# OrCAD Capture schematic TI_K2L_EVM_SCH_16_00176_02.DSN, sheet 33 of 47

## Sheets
33 PAGE46 : K2L_POWER SECTION 5: size C; title: K2L VDDALV, v85 filter, bypass caps, 12v -> 3.3vaux
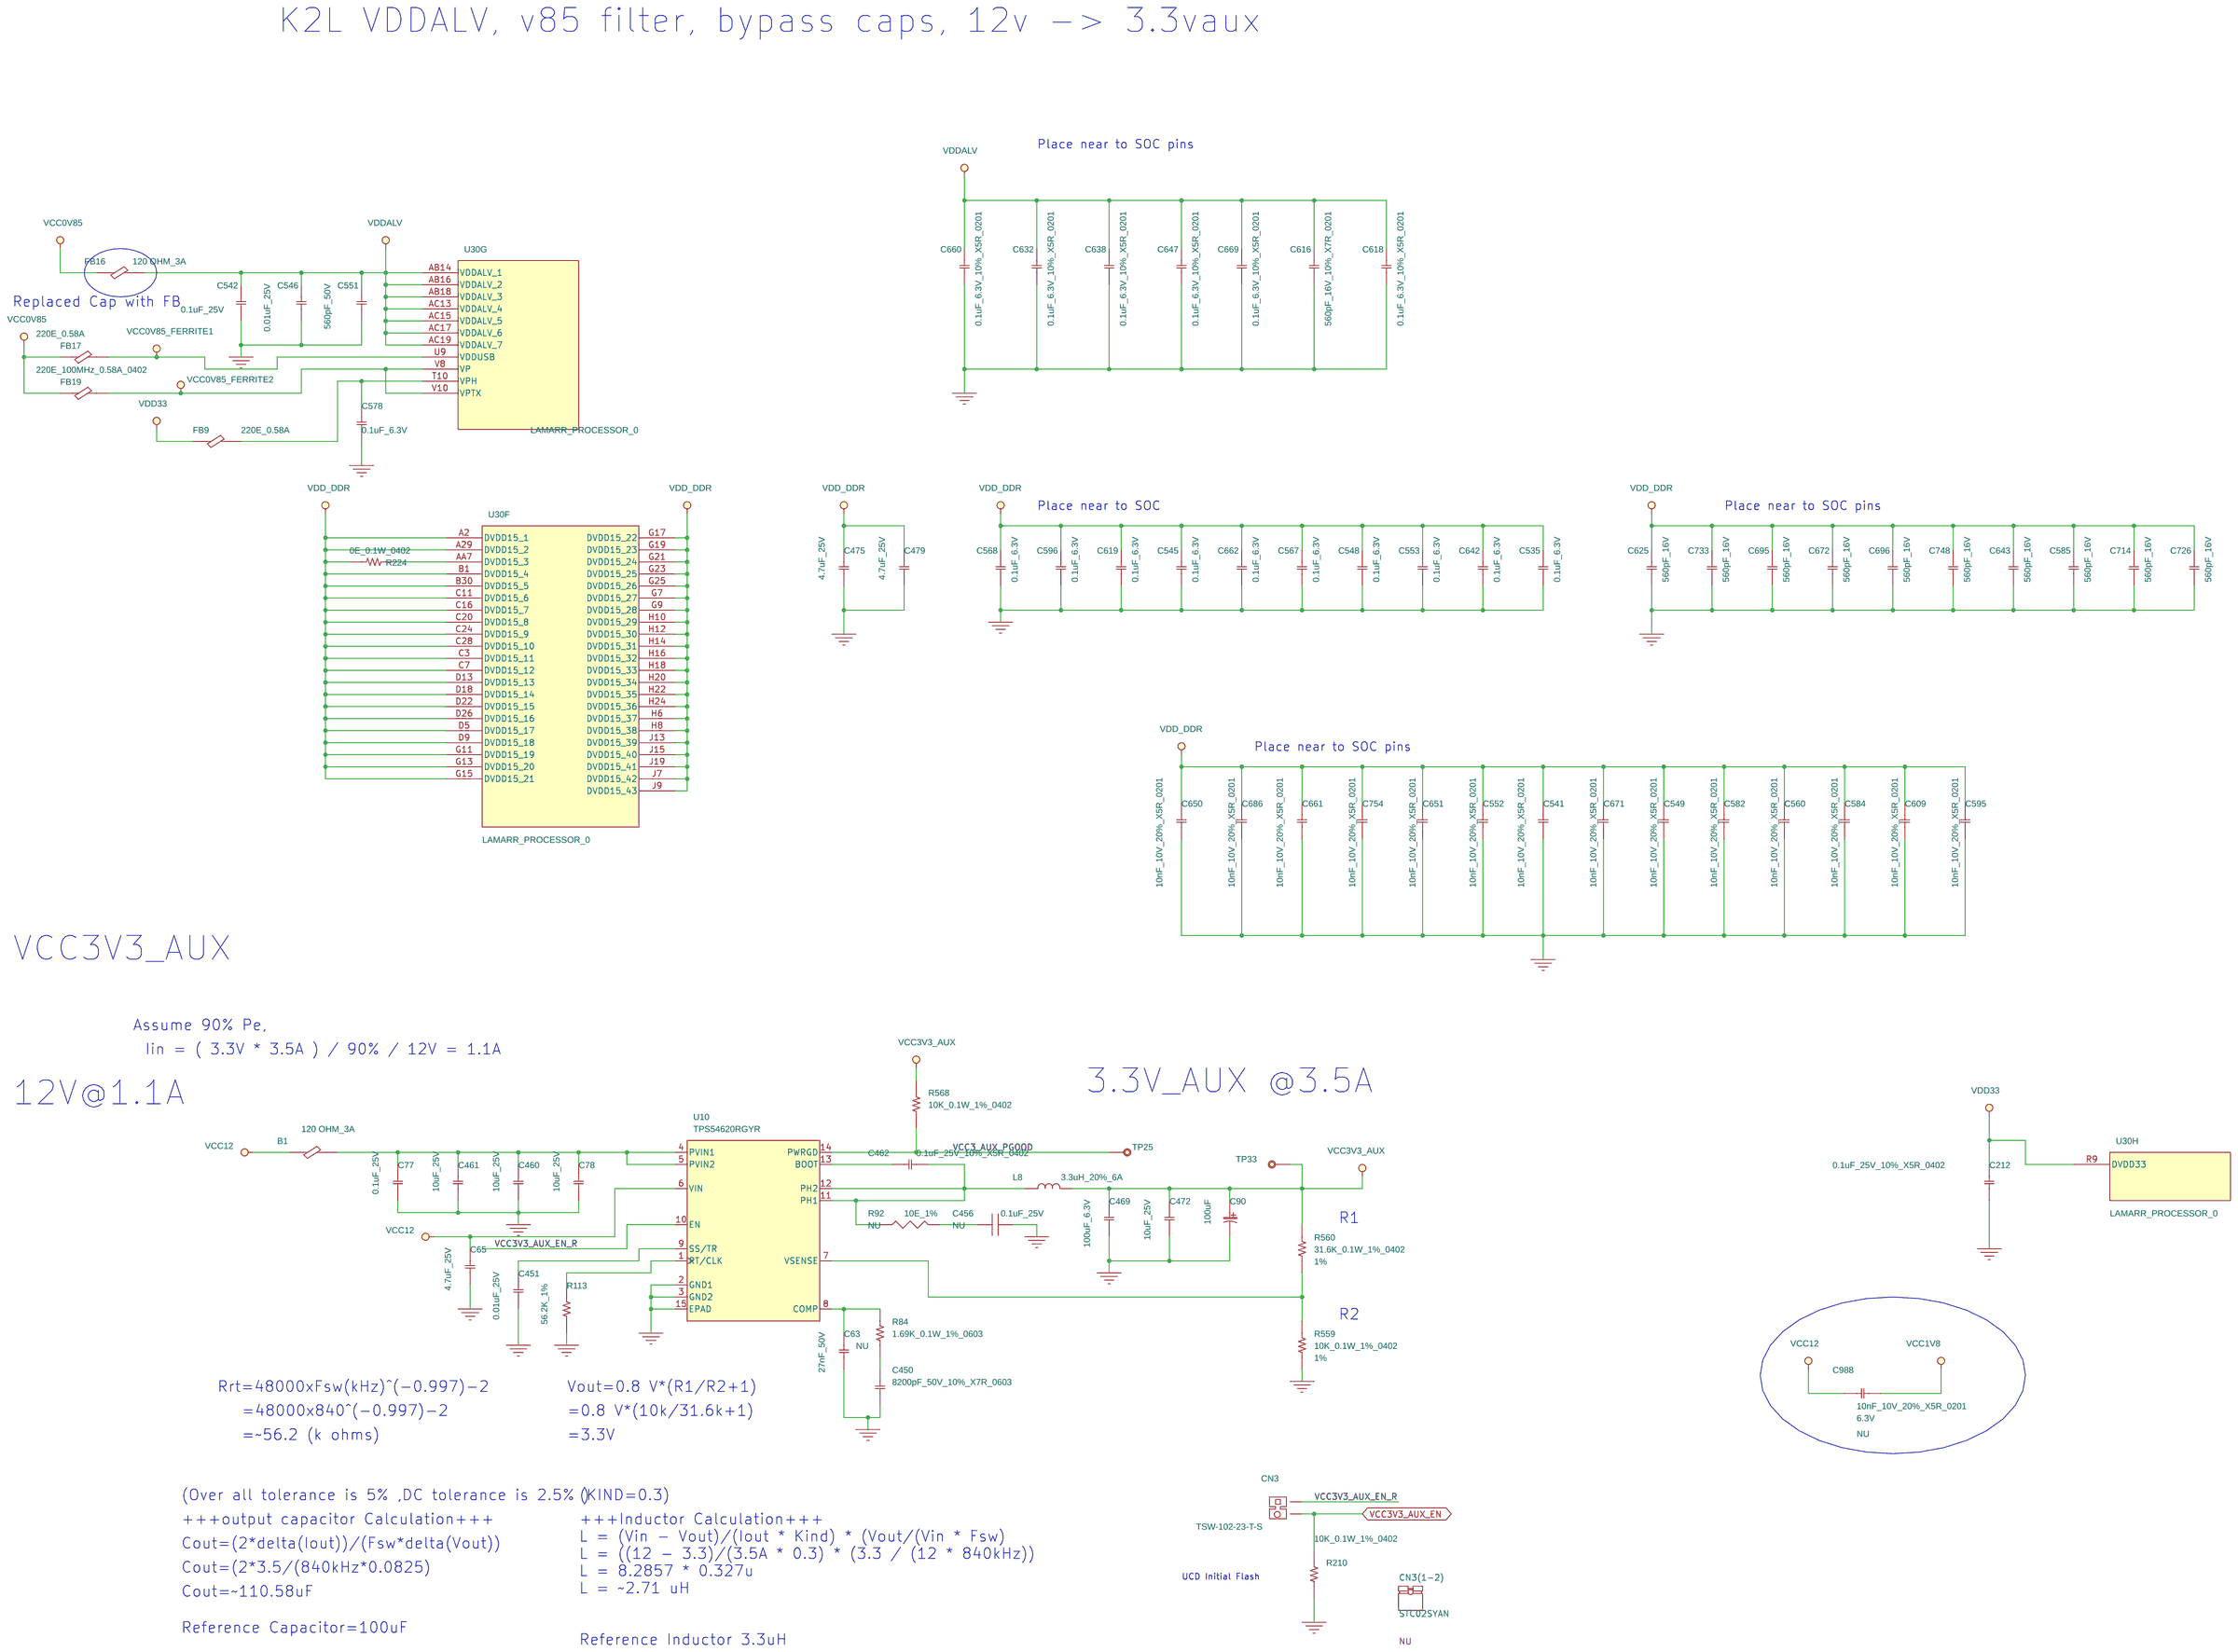
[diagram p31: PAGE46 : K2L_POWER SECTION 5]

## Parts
sheet PAGE24 : K2L_JTAG
U30  LAMARR_PROCESSOR_0  [SKTBGA_Z3566_SS900-RHFB-BGA080]  (sections A,B,C,D,E,F,G,H,I,J,K,L,M,N,O,P,Q,R,S,T,U)
sheet PAGE46 : K2L_POWER SECTION 5
B1  120 OHM_3A  [L0603]
C63  27nF_50V  [C0805]
C65  4.7uF_25V  [C0603]
C77  0.1uF_25V  [C0402]
C78  10uF_25V  [C0603]
C90  100uF  [CT7343]
C212  0.1uF_25V_10%_X5R_0402  [C0402]
C450  8200pF_50V_10%_X7R_0603  [C0603]
C451  0.01uF_25V  [C0402]
C456  0.1uF_25V  [C0402]
C460  10uF_25V  [C0603]
C461  10uF_25V  [C0603]
C462  0.1uF_25V_10%_X5R_0402  [C0402]
C469  100uF_6.3V  [C1206-1]
C472  10uF_25V  [C0603]
C475  4.7uF_25V  [C0603]
C479  4.7uF_25V  [C0603]
C535  0.1uF_6.3V  [CC0201_IPC7351_EINF]
C541  10nF_10V_20%_X5R_0201  [CC0201_IPC7351_EINF]
C542  0.1uF_25V  [C0402]
C545  0.1uF_6.3V  [CC0201_IPC7351_EINF]
C546  0.01uF_25V  [C0402]
C548  0.1uF_6.3V  [CC0201_IPC7351_EINF]
C549  10nF_10V_20%_X5R_0201  [CC0201_IPC7351_EINF]
C551  560pF_50V  [C0402]
C552  10nF_10V_20%_X5R_0201  [CC0201_IPC7351_EINF]
C553  0.1uF_6.3V  [CC0201_IPC7351_EINF]
C560  10nF_10V_20%_X5R_0201  [CC0201_IPC7351_EINF]
C567  0.1uF_6.3V  [CC0201_IPC7351_EINF]
C568  0.1uF_6.3V  [CC0201_IPC7351_EINF]
C578  0.1uF_6.3V  [CC0201_IPC7351_EINF]
C582  10nF_10V_20%_X5R_0201  [CC0201_IPC7351_EINF]
C584  10nF_10V_20%_X5R_0201  [CC0201_IPC7351_EINF]
C585  560pF_16V  [CC0201_IPC7351_EINF]
C595  10nF_10V_20%_X5R_0201  [CC0201_IPC7351_EINF]
C596  0.1uF_6.3V  [CC0201_IPC7351_EINF]
C609  10nF_10V_20%_X5R_0201  [CC0201_IPC7351_EINF]
C616  560pF_16V_10%_X7R_0201  [CC0201_IPC7351_EINF]
C618  0.1uF_6.3V_10%_X5R_0201  [CC0201_IPC7351_EINF]
C619  0.1uF_6.3V  [CC0201_IPC7351_EINF]
C625  560pF_16V  [CC0201_IPC7351_EINF]
C632  0.1uF_6.3V_10%_X5R_0201  [CC0201_IPC7351_EINF]
C638  0.1uF_6.3V_10%_X5R_0201  [CC0201_IPC7351_EINF]
C642  0.1uF_6.3V  [CC0201_IPC7351_EINF]
C643  560pF_16V  [CC0201_IPC7351_EINF]
C647  0.1uF_6.3V_10%_X5R_0201  [CC0201_IPC7351_EINF]
C650  10nF_10V_20%_X5R_0201  [CC0201_IPC7351_EINF]
C651  10nF_10V_20%_X5R_0201  [CC0201_IPC7351_EINF]
C660  0.1uF_6.3V_10%_X5R_0201  [CC0201_IPC7351_EINF]
C661  10nF_10V_20%_X5R_0201  [CC0201_IPC7351_EINF]
C662  0.1uF_6.3V  [CC0201_IPC7351_EINF]
C669  0.1uF_6.3V_10%_X5R_0201  [CC0201_IPC7351_EINF]
C671  10nF_10V_20%_X5R_0201  [CC0201_IPC7351_EINF]
C672  560pF_16V  [CC0201_IPC7351_EINF]
C686  10nF_10V_20%_X5R_0201  [CC0201_IPC7351_EINF]
C695  560pF_16V  [CC0201_IPC7351_EINF]
C696  560pF_16V  [CC0201_IPC7351_EINF]
C714  560pF_16V  [CC0201_IPC7351_EINF]
C726  560pF_16V  [CC0201_IPC7351_EINF]
C733  560pF_16V  [CC0201_IPC7351_EINF]
C748  560pF_16V  [CC0201_IPC7351_EINF]
C754  10nF_10V_20%_X5R_0201  [CC0201_IPC7351_EINF]
C988  10nF_10V_20%_X5R_0201  [CC0201_IPC7351_EINF]
CN3  TSW-102-23-T-S  [SAMTSW-102-22-T-S]
CN3(1-2)  STC02SYAN  [NA]
FB9  220E_0.58A  [L0402]
FB16  120 OHM_3A  [L0603]
FB17  220E_0.58A  [L0402]
FB19  220E_100MHz_0.58A_0402  [L0402]
L8  3.3uH_20%_6A  [IND_ASPI-7318-2R2M-T]
R84  1.69K_0.1W_1%_0603  [R0603]
R92  10E_1%  [R0402]
R113  56.2K_1%  [R0402]
R210  10K_0.1W_1%_0402  [R0402]
R224  0E_0.1W_0402  [R0402]
R559  10K_0.1W_1%_0402  [R0402]
R560  31.6K_0.1W_1%_0402  [R0402]
R568  10K_0.1W_1%_0402  [R0402]
TP25  TP  [TP-S40]
TP33  TP  [TP-S40]
U10  TPS54620RGYR  [QFN_14P_20_138x138_TP79]

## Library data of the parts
U30 = LAMARR_PROCESSOR_7: LAMARR-SoC 900BGA 4DSP + 2ARM; Color: Default; Distributor_name: TBD; Distributor_part_number: TBD; EIC Part#: TBD; Location X-Coordinate: 0; Location Y-Coordinate: 0; Manufacture: TI; Manufacture Part Number: TCI6630K2L; Manufacture(English): TI; Manufacture_Part_Number: TCI6630K2L; Manufacturer: TI; Manufacturer_Part_No: TCI6630K2L; Mfg: TI; Mfg Part#: TBD; Mfr_name: TI; Mfr_part_number: LAMARR-SoC; Price @ 1: TBD; Price @ 10K: TBD; Price @ 1K: TBD; Primitive: DEFAULT; SPLIT_INST: TRUE; SWAP_INFO: (S1+S2+S3+S4+S5+S6+S7+S8+S9+S10+S11+S12+S13+S14+S15+S16+S17+S18+S19+S20+S21); Vendor: TBD; Vendor_Part_No: TBD; eI Part#: TBD
B1 FB16 = 1212_BEAD_0: FILTER CHIP 120 OHM 3A 0603; Distributor_name: DIGIKEY; Distributor_part_number: 490-3996-1-ND; EIC Part#: 04_00405_01; Manufacture: Murata; Manufacture Part Number: BLM18SG121TN1D; Manufacture(English): Murata; Manufacture_Part_Number: BLM18SG121TN1D; Manufacturer: Murata; Manufacturer_Part_No: BLM18SG121TN1D; Mfg: Murata Electronics North America; Mfg Part#: 04_00405_01; Mfr_name: Murata; Mfr_part_number: BLM18SG121TN1D; Part_Number: 1212002506; Price @ 1: 0.14000; Price @ 10K: 0.03173; Price @ 1K: 0.03878; RoHS: Yes; Vendor: DIGIKEY; Vendor Part#: 490-3996-1-ND; Vendor_Part_No: 490-3996-1-ND; eI Part#: 04_00405_01
C63 = 11_C_0: CAP CER 0.027UF 50V 10% X7R 0805; Distributor_name: DIGIKEY; Distributor_part_number: 311-1139-1-ND; EIC Part#: 03_00588_01; Manufacture: Yageo; Manufacture Part Number: CC0805KRX7R9BB273; Manufacture(English): Yageo; Manufacture_Part_Number: CC0805KRX7R9BB273; Manufacturer: Yageo; Manufacturer_Part_No: CC0805KRX7R9BB273; Mfg: Yageo; Mfg Part#: 03_00588_01; Mfr_name: Yageo; Mfr_part_number: CC0805KRX7R9BB273; Mounting Status: NU; Mounting_Status: NU; Oper. Temp. Range: -55C ~ 125C; Package: 0805; Price @ 1: 0.10000; Price @ 10K: 0.01320; Price @ 1K: 0.01722; ProcessType: SMT; RoHS: Yes; Tolerance: 10%; Vendor: DIGIKEY; Vendor Part#: 311-1139-1-ND; Vendor_Part_No: 311-1139-1-ND; Voltage: 50V; eI Part#: 03_00588_01
C65 = 11_C_0: CAP CER 4.7UF 25V 20% X5R 0603; Distributor_name: DIGIKEY; Distributor_part_number: 1276-1903-2-ND; EIC Part#: 03_00592_01; Manufacture: Samsung; Manufacture Part Number: CL10A475MA8NQNC; Manufacture(English): Samsung; Manufacture_Part_Number: CL10A475MA8NQNC; Manufacturer: Samsung; Manufacturer_Part_No: CL10A475MA8NQNC; Mfg: Samsung; Mfg Part#: CL10A475MA8NQNC; Mfr_name: Samsung; Mfr_part_number: CL10A475MA8NQNC; Oper. Temp. Range: -55C to 85C; Package: 0603; Price @ 1: 0.24000; Price @ 10K: 0.05000; Price @ 1K: 0.05875; ProcessType: SMT; RoHS: Yes; Tolerance: 10%; Vendor: DIGIKEY; Vendor Part#: 1276-1903-2-ND; Vendor_Part_No: 1276-1903-2-ND; Voltage: 25V; eI Part#: 03_00592_01
C77 C462 = 11_C_0: CAP CER 0.1UF 25V 10% X5R 0402; Avalue_Part_Number: E1123510400H; Distributor_name: DIGIKEY; Distributor_part_number: 445-4964-1-ND; EIC Part#: 03_00470_02; Manufacture: TDK Corporation; Manufacture Part Number: C1005X5R1E104K050BC; Manufacture(English): TDK Corporation; Manufacture_Part_Number: GRM155R71C104KA88D; Manufacturer: TDK Corporation; Manufacturer_Part_No: C1005X5R1E104K050BC; Mfg: Murata Electronics North America; Mfg Part#: 03_00470_02; Mfr_name: TDK Corporation; Mfr_part_number: C1005X5R1E104K050BC; Package: 0402; Price @ 1: 0.10000; Price @ 1K: 0.00420; ProcessType: SMT; Tolerance: 10%; Vendor: DIGIKEY; Vendor Part#: 445-4964-1-ND; Vendor_Part_No: 445-4964-1-ND; eI Part#: 03_00470_02
C78 C460 C461 = 11_C_0: CAP CER 10UF 25V 20% X5R 0603; Advansus_Part_Number: 11G235210611320; Avalue_Part_Number: E1123510620H; Characteristic: 16V; Distributor_name: DIGIKEY; Distributor_part_number: 445-9015-1-ND; EIC Part#: 03_00609_01; Manufacture: TDK Corporation; Manufacture Part Number: C1608X5R1E106M080AC; Manufacture(English): TDK Corporation; Manufacture_Part_Number: C1608X5R1E106M080AC; Manufacturer: TDK Corporation; Manufacturer_Part_No: C1608X5R1E106M080AC; Mfg: TDK Corporation; Mfg Part#: C1608X5R1E106M080AC; Mfr_name: TDK Corporation; Mfr_part_number: C1608X5R1E106M080AC; Package: 0603; Price @ 1: 0.24000; Price @ 10K: 0.05000; Price @ 1K: 0.05875; ProcessType: SMT; Tolerance: 10%; Vendor: DIGIKEY; Vendor Part#: TDK Corporation; Vendor_Part_No: 445-9015-1-ND; eI Part#: 03_00609_01
C90 = 11_C_POLAR_0: CAP TANT 100UF 20V 10% 2917; Characteristic: 16V; Distributor_name: DIGIKEY; Distributor_part_number: 718-1774-1-ND; EIC Part#: 03_00602_01; Manufacture: Vishay; Manufacture Part Number: TR3D107K020C0080; Manufacture(English): Vishay Dale; Manufacture_Part_Number: TR3D107K020C0080; Manufacturer: Vishay Dale; Manufacturer_Part_No: TR3D107K020C0080; Mfg: Vishay Dale; Mfg Part#: TR3D107K020C0080; Mfr_name: Vishay Dale; Mfr_part_number: TR3D107K020C0080; Package: 7343; Price @ 1: 1.05000; Price @ 10K: 0.29063; Price @ 1K: 0.29063; ProcessType: SMT; RoHS: Yes; Tolerance: 20%; Vendor: DIGIKEY; Vendor Part#: 718-1774-1-ND; Vendor_Part_No: 718-1774-1-ND; eI Part#: 03_00602_01
C212 C542 = 11_C_12: CAP CER 0.1UF 25V 10% X5R 0402; Alt Mfg: Taiyo Yuden; Distributor_name: DIGIKEY; Distributor_part_number: 445-4964-1-ND; EIC Part#: 03_00470_02; Manufacture: TDK Corporation; Manufacture Part Number: C1005X5R1E104K050BC; Manufacture(English): TDK Corporation; Manufacture_Part_Number: GRM155R61E104KA87D; Manufacturer: TDK Corporation; Manufacturer_Part_No: C1005X5R1E104K050BC; Mfg: Murata Electronics North America; Mfg Part#: 03_00470_02; Mfr_name: TDK Corporation; Mfr_part_number: C1005X5R1E104K050BC; Oper. Temp. Range: -55°C ~ 85°C; Package: 0402; Price @ 1: 0.10000; Price @ 1K: 0.00960; ProcessType: SMT; RoHS: Yes; Tolerance: 10%; Vendor: DIGIKEY; Vendor Part#: 445-4964-1-ND; Vendor_Part_No: 445-4964-1-ND; eI Part#: 03_00470_02
C450 = 11_C_0: CAP CER 8200PF 50V 10% X7R 0603; Characteristic: 50V; Distributor_name: DIGIKEY; Distributor_part_number: 490-1510-1-ND; EIC Part#: 03_00232_02; Manufacture: Murata; Manufacture Part Number: GRM188R71H822KA01D; Manufacture(English): Murata; Manufacture_Part_Number: GRM188R71H822KA01D; Manufacturer: Murata; Manufacturer_Part_No: GRM188R71H822KA01D; Mfg: Murata Electronics North America; Mfg Part#: 03_00232_02; Mfr_name: Murata; Mfr_part_number: GRM188R71H822KA01D; Package: 0603; Part_Number: 1124582280; Price @ 1: 0.11000; Price @ 10K: 0.01541; Price @ 1K: 0.02010; ProcessType: SMT; Tolerance: 10%; Vendor: DIGIKEY; Vendor_Part_No: 490-1510-1-ND; eI Part#: 03_00232_02
C451 = 11_C_0: CAP CER 10000PF 25V 10% X7R 0402; Advansus_Part_Number: 11G232110312030; Characteristic: 16V; Distributor_name: DIGIKEY; Distributor_part_number: 445-1260-1-ND; EIC Part#: 03_00029_04; Manufacture: TDK Corporation; Manufacture Part Number: C1005X7R1E103K; Manufacture(English): TDK Corporation; Manufacture_Part_Number: C1005X7R1E103K; Manufacturer: TDK Corporation; Manufacturer_Part_No: C1005X7R1E103K; Mfg: TDK Corporation; Mfg Part#: 03_00029_04; Mfr_name: TDK Corporation; Mfr_part_number: C1005X7R1E103K; Package: 0402; Part_Number: 1121610790; Price @ 1: 0.10000; Price @ 10K: 0.00420; Price @ 1K: 0.00600; ProcessType: SMT; Tolerance: 10%; Vendor: DIGIKEY; Vendor_Part_No: 445-1260-1-ND; eI Part#: 03_00029_04
C456 = CAP_NP: CAP CER 0.1UF 25V 10% X5R 0402; Alt Mfg: Taiyo Yuden; Distributor_name: DIGIKEY; Distributor_part_number: 445-4964-1-ND; EIC Part#: 03_00470_02; Manufacture: TDK Corporation; Manufacture Part Number: C1005X5R1E104K050BC; Manufacture(English): TDK Corporation; Manufacture_Part_Number: GRM155R61E104KA87D; Manufacturer: TDK Corporation; Manufacturer_Part_No: C1005X5R1E104K050BC; Mfg: Murata Electronics North America; Mfg Part#: 03_00470_02; Mfr_name: TDK Corporation; Mfr_part_number: C1005X5R1E104K050BC; Mounting Status: NU; Mounting_Status: NU; Oper. Temp. Range: -55°C ~ 85°C; Package: 0402; Price @ 1: 0.10000; Price @ 1K: 0.00960; RoHS: Yes; Vendor: DIGIKEY; Vendor Part#: 445-4964-1-ND; Vendor_Part_No: 445-4964-1-ND; eI Part#: 03_00470_02
C469 = 11_C_0: CAP CER 100UF 6.3V 20% X5R 1206; Characteristic: 6.3V; Distributor_name: DIGIKEY; Distributor_part_number: 587-1453-1-ND; EIC Part#: 03_00380_04; Manufacture: Taiyo Yuden; Manufacture Part Number: JMK316BJ107ML-T; Manufacture(English): Taiyo Yuden; Manufacture_Part_Number: JMK316BJ107ML-T; Manufacturer: Taiyo Yuden; Manufacturer_Part_No: JMK316BJ107ML-T; Mfg: Taiyo Yuden; Mfg Part#: 03_00380_04; Mfr_name: Taiyo Yuden; Mfr_part_number: JMK316BJ107ML-T; Package: 1206; Part_Number: 1100005026; Price @ 1: 1.80000; Price @ 10K: 0.30450; Price @ 1K: 0.43050; ProcessType: SMT; Tolerance: 20%; Vendor: DIGIKEY; Vendor_Part_No: 587-1453-1-ND; Voltage: 6.3V; eI Part#: 03_00380_04
C472 = 11_C_0: CAP CER 10UF 25V 20% X5R 0603; Characteristic: 6.3V; Distributor_name: DIGIKEY; Distributor_part_number: 445-9015-1-ND; EIC Part#: 03_00609_01; Manufacture: TDK Corporation; Manufacture Part Number: C1608X5R1E106M080AC; Manufacture(English): TDK Corporation; Manufacture_Part_Number: C1608X5R1E106M080AC; Manufacturer: TDK Corporation; Manufacturer_Part_No: C1608X5R1E106M080AC; Mfg: TDK Corporation; Mfg Part#: C1608X5R1E106M080AC; Mfr_name: TDK Corporation; Mfr_part_number: C1608X5R1E106M080AC; Package: 0603; Price @ 1: 0.35000; Price @ 10K: 0.07300; Price @ 1K: 0.08578; ProcessType: SMT; Tolerance: 10%; Vendor: DIGIKEY; Vendor Part#: TDK Corporation; Vendor_Part_No: 445-9015-1-ND; eI Part#: 03_00609_01
C475 C479 = 11_C_12: CAP CER 4.7UF 25V 20% X5R 0603; Characteristic: <Characteristic>; Distributor_name: DIGIKEY; Distributor_part_number: 1276-1903-2-ND; EIC Part#: 03_00592_01; Manufacture: Samsung; Manufacture Part Number: CL10A475MA8NQNC; Manufacture(English): Samsung; Manufacture_Part_Number: CL10A475MA8NQNC; Manufacturer: Samsung; Manufacturer_Part_No: CL10A475MA8NQNC; Mfg: Samsung; Mfg Part#: CL10A475MA8NQNC; Mfr_name: Samsung; Mfr_part_number: CL10A475MA8NQNC; Oper. Temp. Range: -55C to 85C; Package: 0603; Price @ 1: 0.16000; Price @ 10K: 0.02322; Price @ 1K: 0.02970; ProcessType: SMT; RoHS: Yes; Tolerance: 10%; Vendor: DIGIKEY; Vendor Part#: 1276-1903-2-ND; Vendor_Part_No: 1276-1903-2-ND; Voltage: 6.3V; eI Part#: 03_00592_01
C535 C545 C548 C553 C567 C568 C596 C618 C619 C632 C638 C642 C647 C660 C662 C669 = 11_C_12: CAP CER 0.1UF 6.3V 10% X5R 0201; Alt Mfg: Taiyo Yuden; Alt Mfg Part#: TMK105BJ104KV-F; Characteristic: <Characteristic>; Distributor_name: DIGIKEY; Distributor_part_number: 445-1796-1-ND; EIC Part#: 03_00583_01; Manufacture: TDK Corporation; Manufacture Part Number: C0603X5R0J104K030BC; Manufacture(English): TDK Corporation; Manufacture_Part_Number: C0603X5R0J104K030BC; Manufacturer: TDK Corporation; Manufacturer_Part_No: C0603X5R0J104K030BC; Mfg: TDK Corporation; Mfg Part#: 03_00583_01; Mfr_name: TDK Corporation; Mfr_part_number: C0603X5R0J104K030BC; Oper. Temp. Range: -55°C ~ 85°C; Package: 0201; Price @ 1: 0.10000; Price @ 10K: 0.00675; Price @ 1K: 0.00810; ProcessType: SMT; RoHS: Yes; Tolerance: 10%; Vendor: DIGIKEY; Vendor Part#: 445-1796-2-ND; Vendor_Part_No: 445-1796-1-ND; Voltage: 6.3V; eI Part#: 03_00583_01
C541 C549 C552 C560 C582 C584 C595 C609 C650 C651 C661 C671 C686 C754 = 11_C_0: CAP CER 10000PF 10V 20% X5R 0201; Alt Mfg: Murata; Alt Mfg Part#: GRM155R71C103KA01D; Distributor_name: DIGIKEY; Distributor_part_number: 445-4702-1-ND; EIC Part#: 03_00551_02; Manufacture: TDK Corporation; Manufacture Part Number: C0603X5R1A103M030BA; Manufacture(English): TDK Corporation; Manufacture_Part_Number: C0603X5R1A103M030BA; Manufacturer: TDK Corporation; Manufacturer_Part_No: C0603X5R1A103M030BA; Mfg: TDK Corporation; Mfg Part#: 03_00551_02; Mfr_name: TDK Corporation; Mfr_part_number: C0603X5R1A103M030BA; Oper. Temp. Range: -55C to 125C; Package: 0201; Price @ 1: 0.10000; Price @ 10K: 0.00500; Price @ 1K: 0.00600; ProcessType: SMT; RoHS: Yes; Tolerance: 10%; Vendor: DIGIKEY; Vendor Part#: 445-4702-1-ND; Vendor_Part_No: 445-4702-1-ND; Voltage: 6.3V; eI Part#: 03_00551_02
C546 = 11_C_0: CAP CER 10000PF 25V 10% X7R 0402; Alt Mfg: Murata; Alt Mfg Part#: GRM155R71C103KA01D; Distributor_name: DIGIKEY; Distributor_part_number: 445-1260-1-ND; EIC Part#: 03_00029_04; Manufacture: TDK Corporation; Manufacture Part Number: C1005X7R1E103K; Manufacture(English): TDK Corporation; Manufacture_Part_Number: C1005X7R1E103K; Manufacturer: TDK Corporation; Manufacturer_Part_No: C1005X7R1E103K; Mfg: TDK Corporation; Mfg Part#: 03_00029_04; Mfr_name: TDK Corporation; Mfr_part_number: C1005X7R1E103K; Oper. Temp. Range: -55C to 125C; Package: 0402; Price @ 1: 0.10000; Price @ 10K: 0.00420; Price @ 1K: 0.00600; ProcessType: SMT; RoHS: Yes; Tolerance: 10%; Vendor: DIGIKEY; Vendor Part#: PCC103BQCT-ND; Vendor_Part_No: 445-1260-1-ND; Voltage: 16V; eI Part#: 03_00029_04
C551 = 11_C_12: CAP CER 560PF 50V 10% X7R 0402; Avalue_Part_Number: E1127556100H; Characteristic: 50V; Distributor_name: DIGIKEY; Distributor_part_number: 490-1301-1-ND; EIC Part#: 03_00189_02; Manufacture: Murata; Manufacture Part Number: GRM155R71H561KA01D; Manufacture(English): Murata; Manufacture_Part_Number: GRM155R71H561KA01D; Manufacturer: Murata; Manufacturer_Part_No: GRM155R71H561KA01D; Mfg: Murata Electronics North America; Mfg Part#: 03_00189_02; Mfr_name: Murata; Mfr_part_number: GRM155R71H561KA01D; Oper. Temp. Range: -55°C ~ 125°C; Package: 0402; Price @ 1: 0.10000; Price @ 10K: 0.00672; Price @ 1K: 0.00960; ProcessType: SMT; RoHS: Yes; Tolerance: 10%; Vendor: DIGIKEY; Vendor Part#: 490-1301-1-ND; Vendor_Part_No: 490-1301-1-ND; Voltage: 50V; eI Part#: 03_00189_02
C578 = Cap_Ceramic: CAP CER 0.1UF 6.3V 10% X5R 0201; Alt Mfg: Taiyo Yuden; Alt Mfg Part#: TMK105BJ104KV-F; Characteristic: <Characteristic>; Distributor_name: DIGIKEY; Distributor_part_number: 445-1796-1-ND; EIC Part#: 03_00583_01; Manufacture: TDK Corporation; Manufacture Part Number: C0603X5R0J104K030BC; Manufacture(English): TDK Corporation; Manufacture_Part_Number: TBD; Manufacturer: TDK Corporation; Manufacturer_Part_No: C0603X5R0J104K030BC; Mfg: TDK Corporation; Mfg Part#: 03_00583_01; Mfr_name: TDK Corporation; Mfr_part_number: C0603X5R0J104K030BC; Oper. Temp. Range: -55°C ~ 85°C; Package: 0201; ProcessType: SMT; RoHS: Yes; Tolerance: 10%; Vendor: DIGIKEY; Vendor Part#: 445-1796-2-ND; Vendor_Part_No: 445-1796-1-ND; eI Part#: 03_00583_01
C585 C616 C625 C643 C672 C695 C696 C714 C726 C733 C748 = 11_C_12: CAP CER 560PF 16V 10% X7R 0201; Avalue_Part_Number: E1127556100H; Characteristic: 50V; Distributor_name: DIGIKEY; Distributor_part_number: 1276-1357-1-ND; EIC Part#: 03_00590_01; Manufacture: Samsung; Manufacture Part Number: CL03B561KO3NNNC; Manufacture(English): Samsung; Manufacture_Part_Number: CL03B561KO3NNNC; Manufacturer: Samsung; Manufacturer_Part_No: CL03B561KO3NNNC; Mfg: Samsung; Mfg Part#: 03_00590_01; Mfr_name: Samsung; Mfr_part_number: CL03B561KO3NNNC; Oper. Temp. Range: -55°C ~ 125°C; Package: 0201; Price @ 1: 0.10000; Price @ 10K: 0.00441; Price @ 1K: 0.00630; ProcessType: SMT; RoHS: Yes; Tolerance: 10%; Vendor: DIGIKEY; Vendor Part#: 1276-1357-1-ND; Vendor_Part_No: 1276-1357-1-ND; Voltage: 16V; eI Part#: 03_00590_01
C988 = 11_C_0: CAP CER 10000PF 10V 20% X5R 0201; Alt Mfg: Murata; Alt Mfg Part#: GRM155R71C103KA01D; Distributor_name: DIGIKEY; Distributor_part_number: 445-4702-1-ND; EIC Part#: 03_00551_02; Manufacture: TDK Corporation; Manufacture Part Number: C0603X5R1A103M030BA; Manufacture(English): TDK Corporation; Manufacture_Part_Number: C0603X5R1A103M030BA; Manufacturer: TDK Corporation; Manufacturer_Part_No: C0603X5R1A103M030BA; Mfg: TDK Corporation; Mfg Part#: 03_00551_02; Mfr_name: TDK Corporation; Mfr_part_number: C0603X5R1A103M030BA; Mounting Status: NU; Mounting_Status: NU; Oper. Temp. Range: -55C to 125C; Package: 0201; Price @ 1: 0.10000; Price @ 10K: 0.00500; Price @ 1K: 0.00600; ProcessType: SMT; RoHS: Yes; Tolerance: 10%; Vendor: DIGIKEY; Vendor Part#: 445-4702-1-ND; Vendor_Part_No: 445-4702-1-ND; Voltage: 6.3V; eI Part#: 03_00551_02
CN3 = 1653_HD_2P_D_0: CONN HEADER 2POS .100 SNGL TIN; AVL_Part: AVL; Advansus_Part_Number: 12G06010002DAD; Avalue_Part_Number: E1653002101R; Distributor_name: DIGIKEY; Distributor_part_number: SAM1075-02-ND; EIC Part#: 09_00957_01; Manufacture: Samtec Inc; Manufacture(English): Samtec Inc; Manufacturer: Samtec Inc; Mfg: Samtec Inc; Mfg Part#: 09_00957_01; Mfr_name: Samtec Inc; Package: PH2x1P-2.00; Part_Number: 1653002101-03; Price @ 1: 0.49000; Price @ 10K: 0.21284; Price @ 1K: 0.24263; ProcessType: DIP; Vendor: DIGIKEY; Vendor_Part_No: SAM1075-02-ND; eI Part#: TBD
CN3(1-2) = 1653_MINIJUMPER22.0MM_0: CONN JUMPER SHORTING TIN; Distributor_name: DIGIKEY; Distributor_part_number: S9000-ND; EIC Part#: 09_00190_01; Manufacture: Sullins Connector; Manufacture(English): Sullins Connector; Manufacturer: Sullins Connector; Mfg: Sullins Connector Solutions; Mfg Part#: 09_00190_01; Mfr_name: Sullins Connector; Mounting Status: NU; Mounting_Status: NU; Package: MINIJUMPER2P-2.00; Part_Number: 1653302122; Price @ 1: 0.29000; Price @ 10K: 0.04800; Price @ 1K: 0.06080; ProcessType: DIP; Vendor: DIGIKEY; Vendor_Part_No: S9000-ND; eI Part#: 09_00190_01
FB9 FB17 FB19 = 1212_BEAD_0: FERRITE CHIP 220 OHM 0402; AVL_Part: AVL; Characteristic: 0.58A; Distributor_name: DIGIKEY; Distributor_part_number: 490-5440-1-ND; EIC Part#: TBD; Manufacture: Murata; Manufacture Part Number: BLM15AX221SN1D; Manufacture(English): Murata; Manufacture_Part_Number: BLM15AX221SN1D; Manufacturer: Murata; Manufacturer_Part_No: BLM15AX221SN1D; Mfg: Murata Electronics North America; Mfg Part#: TBD; Mfr_name: Murata; Mfr_part_number: BLM15AX221SN1D; Package: 0402; Part_Number: 1212002796-01; Price @ 1: 0.11000; Price @ 10K: 0.02296; Price @ 1K: 0.02886; ProcessType: SMT; Tolerance: 25%; Vendor: DIGIKEY; Vendor_Part_No: 490-5440-1-ND; eI Part#: TBD
L8 = 1211_CHOKE_0: INDUCTOR SHIELD 3.3UH SMD; AVL_Part: Non-AVL; Avalue_Part_Number: E1212203328H; Characteristic: 6A; Distributor_name: DIGIKEY; Distributor_part_number: ASPI-7318-3R3M-TCT-ND; EIC Part#: TBD; Manufacture: Abracon Corporation; Manufacture Part Number: ASPI-7318-3R3M-T; Manufacture(English): Abracon Corporation; Manufacture_Part_Number: ASPI-7318-3R3M-T; Manufacturer: Abracon Corporation; Manufacturer_Part_No: ASPI-7318-3R3M-T; Mfg: Abracon Corporation; Mfg Part#: TBD; Mfr_name: Abracon Corporation; Mfr_part_number: ASPI-7318-3R3M-T; Package: 7.3*6.6*3.0mm; Part_Number: 1211001720; Price @ 1: 1.05000; Price @ 10K: 0.63000; Price @ 1K: 0.63000; ProcessType: SMT; Tolerance: 20%; Vendor: DIGIKEY; Vendor_Part_No: ASPI-7318-3R3M-TCT-ND; eI Part#: TBD
R84 = 10_R_0: RES 1.69K OHM 1/10W 1% 0603 SMD; Characteristic: 1%; Distributor_name: DIGIKEY; Distributor_part_number: P1.69KHCT-ND; EIC Part#: 02_00738_01; Manufacture: Panasonic - ECG; Manufacture Part Number: ERJ-3EKF1691V; Manufacture(English): Panasonic - ECG; Manufacture_Part_Number: ERJ-3EKF1691V; Manufacturer: Panasonic - ECG; Manufacturer_Part_No: ERJ-3EKF1691V; Mfg: Panasonic Electronic Components; Mfg Part#: 02_00738_01; Mfr_name: Panasonic - ECG; Mfr_part_number: ERJ-3EKF1691V; Package: 0603; Part_Number: 105A516913; Price @ 1: 0.10000; Price @ 10K: 0.00247; Price @ 1K: 0.00416; ProcessType: SMT; Tolerance: 1%; Vendor: DIGIKEY; Vendor_Part_No: P1.69KHCT-ND; eI Part#: 02_00738_01
R92 = RESISTOR: RES 10.0 OHM 1/10W 1% 0402 SMD; Alt Mfg: Yageo; Alt Mfg Part#: RC0402FR-0710RL; Distributor_name: DIGIKEY; Distributor_part_number: P10.0LCT-ND; EIC Part#: 02_00348_01; Manufacture: Panasonic - ECG; Manufacture Part Number: ERJ-2RKF10R0X; Manufacture(English): Panasonic - ECG; Manufacture_Part_Number: ERJ-2RKF10R0X; Manufacturer: Panasonic - ECG; Manufacturer_Part_No: ERJ-2RKF10R0X; Mfg: Panasonic Electronic Components; Mfg Part#: 02_00348_01; Mfr_name: Panasonic - ECG; Mfr_part_number: ERJ-2RKF10R0X; Mounting Status: NU; Mounting_Status: NU; Oper. Temp. Range: -55C to 125C; Package: 0402; Price @ 1: 0.10000; Price @ 10K: 0.00347; Price @ 1K: 0.00672; RoHS: Yes; Specifications: RES 10.0 OHM 1/10W 1% 0402 SMD; Tolerance: 1%; Vendor: DIGIKEY; Vendor Part#: P10.0LCT-ND; Vendor_Part_No: P10.0LCT-ND; eI Part#: 02_00019_01
R113 = 10_R_0: RES 56.2K OHM 1/16W 1% 0402 SMD; Characteristic: 1%; Distributor_name: DIGIKEY; Distributor_part_number: P56.2KLCT-ND; EIC Part#: 02_00391_01; Manufacture: Panasonic - ECG; Manufacture Part Number: ERJ-2RKF5622X; Manufacture(English): Panasonic - ECG; Manufacture_Part_Number: ERJ-2RKF5622X; Manufacturer: Panasonic - ECG; Manufacturer_Part_No: ERJ-2RKF5622X; Mfg: Panasonic Electronic Components; Mfg Part#: 02_00391_01; Mfr_name: Panasonic - ECG; Mfr_part_number: ERJ-2RKF5622X; Package: 0402; Part_Number: 1000000620; Price @ 1: 0.10000; Price @ 10K: 0.00347; Price @ 1K: 0.00672; ProcessType: SMT; Tolerance: 1%; Vendor: DIGIKEY; Vendor_Part_No: P56.2KLCT-ND; eI Part#: 02_00391_01
R210 R559 R568 = 10_R_0: RES 10K OHM 1/10W 1% 0402 SMD; Characteristic: 1%; Distributor_name: DIGIKEY; Distributor_part_number: P10.0KLCT-ND; EIC Part#: 02_00027_01; Manufacture: Panasonic - ECG; Manufacture Part Number: ERJ-2RKF1002X; Manufacture(English): Panasonic - ECG; Manufacture_Part_Number: ERJ-2RKF1002X; Manufacturer: Panasonic - ECG; Manufacturer_Part_No: ERJ-2RKF1002X; Mfg: PANASONIC ELECTRONIC COMPONENTS (VA); Mfg Part#: 02_00027_01; Mfr_name: Panasonic - ECG; Mfr_part_number: ERJ-2RKF1002X; Package: 0402; Part_Number: 105A50103A; Price @ 1: 0.10000; Price @ 10K: 0.00347; Price @ 1K: 0.00672; ProcessType: SMT; Tolerance: 1%; Vendor: DIGIKEY; Vendor_Part_No: P10.0KLCT-ND; eI Part#: 02_00027_01
R224 = 10_R_0: RES 0.0 OHM 1/10W JUMP 0402 SMD; Characteristic: 5%; Distributor_name: DIGIKEY; Distributor_part_number: P0.0JCT-ND; EIC Part#: 02_00019_01; Manufacture: Panasonic - ECG; Manufacture Part Number: ERJ-2GE0R00X; Manufacture(English): Panasonic - ECG; Manufacture_Part_Number: ERJ-2GE0R00X; Manufacturer: Panasonic - ECG; Manufacturer_Part_No: ERJ-2GE0R00X; Mfg: Panasonic Electronic Components; Mfg Part#: 02_00019_01; Mfr_name: Panasonic - ECG; Mfr_part_number: ERJ-2GE0R00X; Package: 0402; Part_Number: 105A700004; Price @ 1: 0.05000; Price @ 10K: 0.00248; Price @ 1K: 0.00480; ProcessType: SMT; Tolerance: 5%; Vendor: DIGIKEY; Vendor_Part_No: P0.0JCT-ND; eI Part#: 02_00019_01
R560 = 10_R_0: RES 31.6K OHM 1/10W 1% 0402 SMD; Characteristic: 1%; Distributor_name: DIGIKEY; Distributor_part_number: P31.6KLCT-ND; EIC Part#: 02_00319_01; Manufacture: Panasonic - ECG; Manufacture Part Number: ERJ-2RKF3162X; Manufacture(English): Panasonic - ECG; Manufacture_Part_Number: ERJ-2RKF3162X; Manufacturer: Panasonic - ECG; Manufacturer_Part_No: ERJ-2RKF3162X; Mfg: Panasonic Electronic Components; Mfg Part#: 02_00319_01; Mfr_name: Panasonic - ECG; Mfr_part_number: ERJ-2RKF3162X; Package: 0402; Part_Number: 1000000181; Price @ 1: 0.10000; Price @ 10K: 0.00347; Price @ 1K: 0.00672; ProcessType: SMT; Tolerance: 1%; Vendor: DIGIKEY; Vendor_Part_No: P31.6KLCT-ND; eI Part#: 02_00319_01
TP25 TP33 = 00_TP28_0: TEST PAD TP; Advansus_Part_Number: 0030000003; Avalue_Part_Number: 0030000003; Distributor_name: NA; Distributor_part_number: NA; EIC Part#: NA; Manufacture: NA; Manufacture Part Number: NA; Manufacture(English): NA; Manufacture_Part_Number: NA; Manufacturer: NA; Manufacturer_Part_No: NA; Mfg: NA; Mfg Part#: NA; Mfr_name: NA; Mfr_part_number: NA; Part_Number: 0030000003; Price @ 1: NA; Price @ 10K: NA; Price @ 1K: NA; ProcessType: SMT; Vendor: NA; Vendor_Part_No: NA; eI Part#: NA
U10 = TPS54620RGY: IC REG BUCK SYNC ADJ 6A 14VQFN; Distributor_name: DIGIKEY; Distributor_part_number: 296-24554-1-ND; EIC Part#: 01_00391_01; Manufacture: TI; Manufacture(English): TI; Manufacturer: TI; Mfg: TI; Mfg Part#: 01_00391_01; Mfr_name: TI; Oper. Temp. Range: -40°C ~ 150°C; Package: QFN14; Price @ 1: 6.48000; Price @ 10K: 2.81250; Price @ 1K: 2.86875; ProcessType: SMT; RoHS: Yes; Vendor: DIGIKEY; Vendor Part#: 296-24554-1-ND; Vendor_Part_No: 296-24554-1-ND; eI Part#: TBD

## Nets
GND: C63.2 C65.2 C77.2 C78.2 C90.2 C212.2 C450.2 C451.2 C456.1 C460.2 C461.2 C469.2 C472.2 C475.2 C479.2 C535.2 C541.2 C542.2 C545.2 C546.2 C548.2 C549.2 C551.2 C552.2 C553.2 C560.2 C567.2 C568.2 C578.2 C582.2 C584.2 C585.2 C595.2 C596.2 C609.2 C616.2 C618.2 C619.2 C625.2 C632.2 C638.2 C642.2 C643.2 C647.2 C650.2 C651.2 C660.2 C661.2 C662.2 C669.2 C671.2 C672.2 C686.2 C695.2 C696.2 C714.2 C726.2 C733.2 C748.2 C754.2 R113.1 R210.1 R559.2 U10.2(GND1) U10.3(GND2) U10.15(EPAD) ; also on sheet 1 2 3 4 5 6 8 10 11 12 13 14 15 16 17 18 19 20 21 22 24 25 26 27 28 29 34 35 36 37 40 41 42 43 45 46 47
VCC0V85: FB16.1 FB17.1 FB19.1 ; also on sheet 34 37
VCC0V85_FERRITE1: FB17.2 U30.U9(VDDUSB)
VCC0V85_FERRITE2: FB19.2 U30.V8(VP) U30.V10(VPTX)
VCC1V8: C988.2 ; also on sheet 2 6 8 11 19 21 22 25 26 27 29 34 36 37 41
VCC3_AUX_PGOOD: R568.1 TP25.1 U10.14(PWRGD)
VCC3V3_AUX: C90.1 C469.1 C472.1 L8.2 R560.1 R568.2 TP33.1 ; also on sheet 2 4 6 8 11 12 13 16 18 19 22 25 26 27 28 29 35 37 40 45 47
VCC3V3_AUX_EN: CN3.2 R210.2 ; also on sheet 37
VCC3V3_AUX_EN_R: CN3.1 U10.10(EN)
VCC12: B1.1 C65.1 C988.1 U10.6(VIN) ; also on sheet 25 34 35
VDD33: C212.1 FB9.1 U30.R9(DVDD33) ; also on sheet 25
VDD_DDR: C475.1 C479.1 C535.1 C541.1 C545.1 C548.1 C549.1 C552.1 C553.1 C560.1 C567.1 C568.1 C582.1 C584.1 C585.1 C595.1 C596.1 C609.1 C619.1 C625.1 C642.1 C643.1 C650.1 C651.1 C661.1 C662.1 C671.1 C672.1 C686.1 C695.1 C696.1 C714.1 C726.1 C733.1 C748.1 C754.1 R224.2 U30.A2(DVDD15_1) U30.A29(DVDD15_2) U30.B1(DVDD15_4) U30.B30(DVDD15_5) U30.C3(DVDD15_11) U30.C7(DVDD15_12) U30.C11(DVDD15_6) U30.C16(DVDD15_7) U30.C20(DVDD15_8) U30.C24(DVDD15_9) U30.C28(DVDD15_10) U30.D5(DVDD15_17) U30.D9(DVDD15_18) U30.D13(DVDD15_13) U30.D18(DVDD15_14) U30.D22(DVDD15_15) U30.D26(DVDD15_16) U30.G7(DVDD15_27) U30.G9(DVDD15_28) U30.G11(DVDD15_19) U30.G13(DVDD15_20) U30.G15(DVDD15_21) U30.G17(DVDD15_22) U30.G19(DVDD15_23) U30.G21(DVDD15_24) U30.G23(DVDD15_25) U30.G25(DVDD15_26) U30.H6(DVDD15_37) U30.H8(DVDD15_38) U30.H10(DVDD15_29) U30.H12(DVDD15_30) U30.H14(DVDD15_31) U30.H16(DVDD15_32) U30.H18(DVDD15_33) U30.H20(DVDD15_34) U30.H22(DVDD15_35) U30.H24(DVDD15_36) U30.J7(DVDD15_42) U30.J9(DVDD15_43) U30.J13(DVDD15_39) U30.J15(DVDD15_40) U30.J19(DVDD15_41) ; also on sheet 1 19 20 35 37
VDDALV: C542.1 C546.1 C551.1 C616.1 C618.1 C632.1 C638.1 C647.1 C660.1 C669.1 FB16.2 U30.AB14(VDDALV_1) U30.AB16(VDDALV_2) U30.AB18(VDDALV_3) U30.AC13(VDDALV_4) U30.AC15(VDDALV_5) U30.AC17(VDDALV_6) U30.AC19(VDDALV_7)
N19377969: B1.2 C77.1 C78.1 C460.1 C461.1 U10.4(PVIN1) U10.5(PVIN2)
N19379166: C451.1 U10.9(SS/TR)
N19379894: R113.2 U10.1(RT/CLK)
N19380926: C63.1 R84.1 U10.8(COMP)
N19380928: C450.1 R84.2
N19381836: C462.1 U10.13(BOOT)
N19381838: C462.2 L8.1 R92.2 U10.11(PH1) U10.12(PH2)
N19382736: R559.1 R560.2 U10.7(VSENSE)
N19384013: C456.2 R92.1
N21093747: R224.1 U30.AA7(DVDD15_3)
N21894238: C578.1 FB9.2 U30.T10(VPH)

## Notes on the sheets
sheet 33
- K2L VDDALV, v85 filter, bypass caps, 12v -> 3.3vaux
- Place near to SOC pins
- Replaced Cap with FB
- Place near to SOC
- Place near to SOC pins
- Place near to SOC pins
- VCC3V3_AUX
- Assume 90% Pe,
- Iin = ( 3.3V * 3.5A ) / 90% / 12V = 1.1A
- 12V@1.1A
- 3.3V_AUX @3.5A
- R1
- R2
- Rrt=48000xFsw(kHz)^(-0.997)-2
- Vout=0.8 V*(R1/R2+1)
- =48000x840^(-0.997)-2
- =0.8 V*(10k/31.6k+1)
- =~56.2 (k ohms)
- =3.3V
- (Over all tolerance is 5% ,DC tolerance is 2.5% )
- (KIND=0.3)
- +++output capacitor Calculation+++
- +++Inductor Calculation+++
  L = (Vin - Vout)/(Iout * Kind) * (Vout/(Vin * Fsw)
  L = ((12 - 3.3)/(3.5A * 0.3) * (3.3 / (12 * 840kHz))
  L = 8.2857 * 0.327u
  L = ~2.71 uH
- Cout=(2*delta(Iout))/(Fsw*delta(Vout))
- Cout=(2*3.5/(840kHz*0.0825)
- UCD Initial Flash
- Cout=~110.58uF
- Reference Capacitor=100uF
- Reference Inductor 3.3uH
